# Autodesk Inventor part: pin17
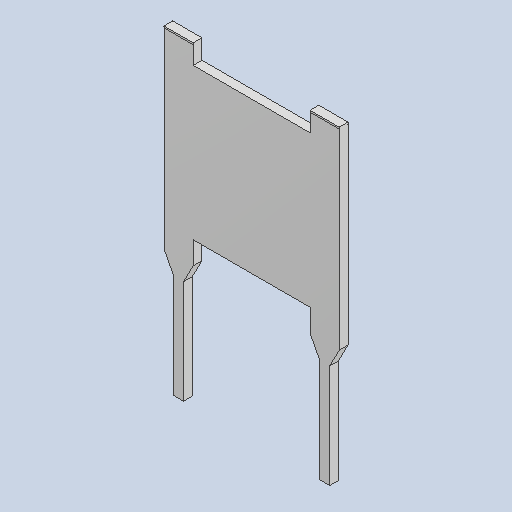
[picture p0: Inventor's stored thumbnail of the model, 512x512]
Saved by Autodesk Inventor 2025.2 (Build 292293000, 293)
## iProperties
Created: 2025-04
Part Number: pin17
Material: Generic
Description: PART--DESC
Document SubType Name: Modeling
Designer: BennF
Density: 1 g/cm^3
Appearance: Default
Author: BennF
Revision Number: NONE
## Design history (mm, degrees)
feature "Solid"
body "Solid1"
